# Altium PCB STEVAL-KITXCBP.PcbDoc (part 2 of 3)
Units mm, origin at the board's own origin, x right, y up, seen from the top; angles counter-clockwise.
Board outline 265 x 224 mm, 4 copper layers (Top Layer, GND, PWR, Bottom Layer), stack 1.55 mm thick; 241 components, 114 nets, 595 pads, 236 vias.
Unrouted connection lines stored in the file: 2.
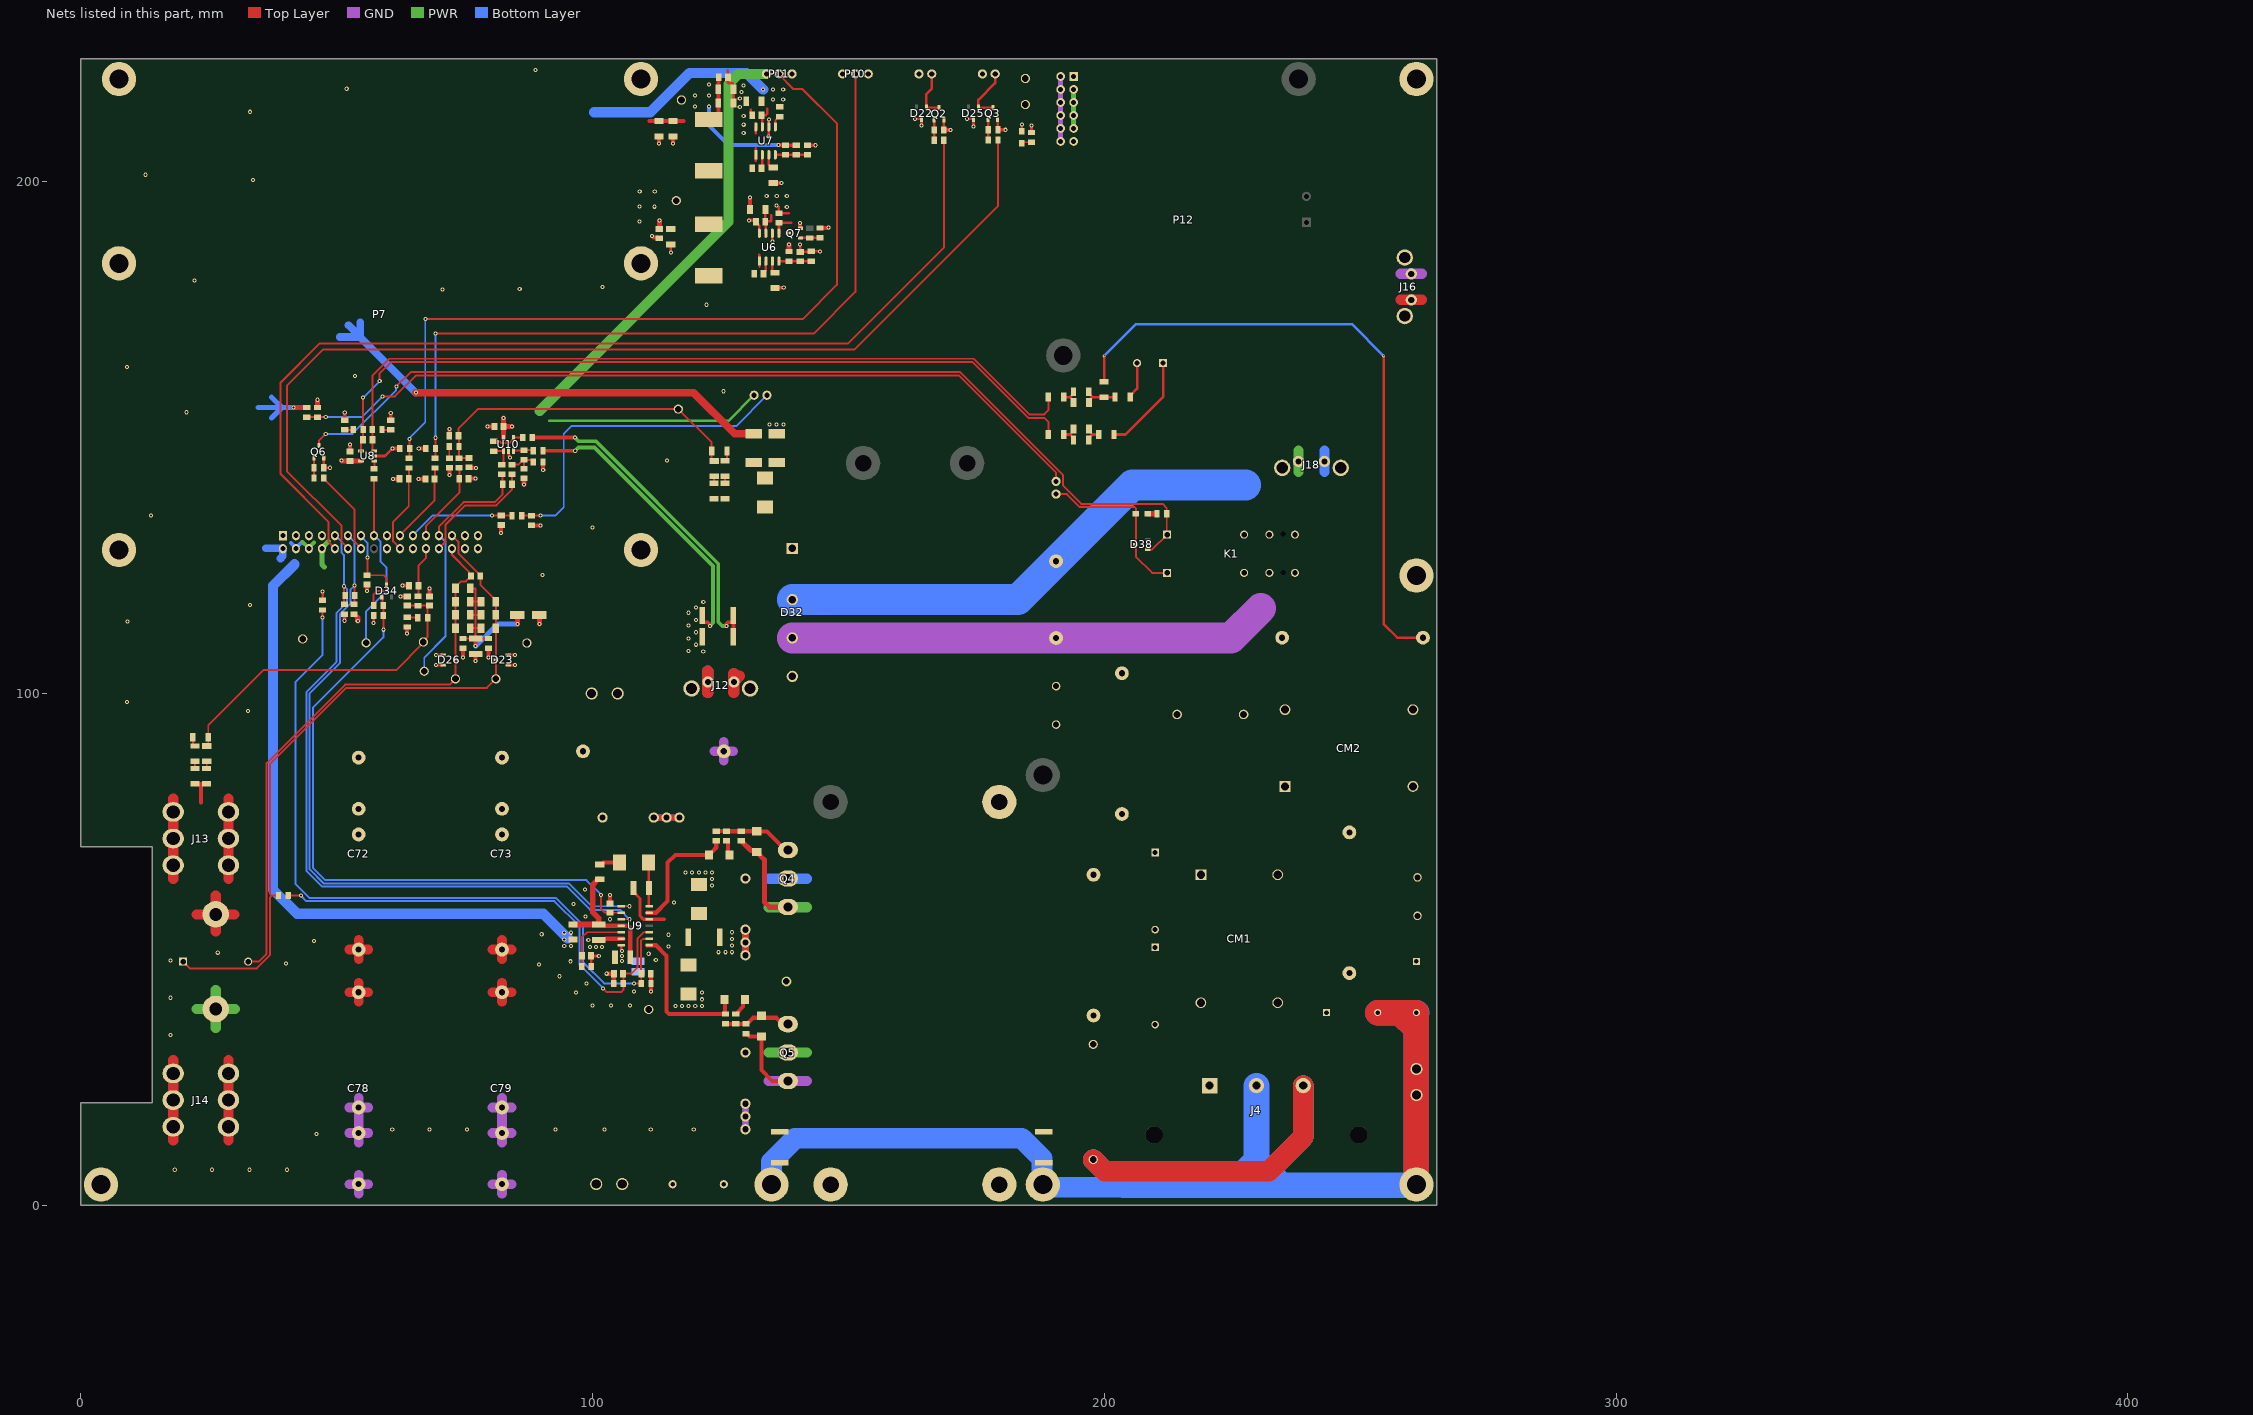
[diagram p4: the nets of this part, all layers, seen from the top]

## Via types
v1: diameter 0.8, hole 0.4, Top Layer to Bottom Layer, tented both sides, 234 vias
v2: diameter 0.6, hole 0.3, Top Layer to Bottom Layer, tented both sides, 2 vias

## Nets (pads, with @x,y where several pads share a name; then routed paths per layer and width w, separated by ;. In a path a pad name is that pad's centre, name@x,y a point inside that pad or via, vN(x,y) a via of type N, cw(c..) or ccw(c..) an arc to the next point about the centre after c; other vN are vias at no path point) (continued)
+3V3: C55.1 C84.2 D23.2 D26.2 P7.8 P9.2 P10.1 P11.1 R70.2 R79.2 R84.2 R93.2 R101.2 U8.5 U10.5 | length 154.8
  Top Layer w0.5: R70.2@47.3,118.15 v1(47.3,119.851) ; v1(57.251,113.749) R93.2@57.251,115.196
  Top Layer w0.6: v1(69.482,105.55) D26.2@70.85,105.55 ; D23.2@83.55,107.45 v1(84.918,107.45)
  Top Layer w0.762: v1(79.7,107.013) R79.2@79.7,108.8
  Top Layer w1: v1(51.018,145.451) 51.064,145.406 C55.1@52.648,145.406 U8.5@54.802,145.406 ; R84.2@53.45,115.45 54.161,114.739 54.161,114.104 v1(54.164,114.101) ; U10.5@82.658,149.92 82.664,149.925 82.664,152.113 C84.2@82.669,152.119 ; v1(82.658,153.744) 82.669,153.734 C84.2@82.669,152.119 ; v1(84.258,152.113) 84.253,152.119 C84.2@82.669,152.119 ; v1(86.656,140.767) R101.2@86.656,141.994
  PWR w0.5: 91.6,153.2 126.575,153.2 P9.2@131.6,158.225
  PWR w1: 47.601,124.683 47.15,125.134 47.15,128.358 48.412,129.62
  PWR w2: 89.7,155.2 126.6,192.1 126.6,219 128.6,221 P11.1@134,221
  other v1: 90.272,123.088
+5V: C40.2 C41.2 C89.2 C91.2 C92.2 C93.2 L4.1 P7.6 R31.2 TP10.1 | length 42
  Top Layer w0.762: 111.173,211.777 C91.2@113.039,211.777 C92.2@115.731,211.777 117.815,211.777 ; L4.1@122.7,212.1 123.519,212.1 124.638,213.219 124.638,220.282 C41.2@124.676,220.32 C41.2@124.498,220.497 ; v1(136.335,207.084) 137.704,207.084 137.727,207.061 139.814,207.061 C93.2@139.837,207.038
  PWR w0.762: 43.398,129.546 44.602,128.342 44.61,128.342 44.61,128.49 45.589,129.469
  Bottom Layer w0.762: v1(122.784,214.651) 122.784,210.928 126.628,207.084 v1(136.335,207.084)
  other v1: 120.04,214.651 120.04,216.782 122.784,216.782 122.784,218.913
+16V: C35.2 C88.2 L3.1 P7.4 R24.2 R81.1 R82.2 R98.2 TP9.1 | length 229
  Top Layer w1: R98.2@46.288,155.832 v1@46.288,157.211 ; C88.2@113.1,190.702 113.1,192.314 v1@113.111,192.325 ; R24.2@138.445,186.306 v1(138.445,187.647)
  Top Layer w1.5: v1(65.506,158.732) 119.759,158.732 127.791,150.7 R81.1@131.5,150.7
  Bottom Layer w0.762: 41.082,129.33 42.07,128.342 43.182,129.454
  Bottom Layer w1.5: 50.62,169.586 54.652,169.586 ; 52.359,171.879 54.652,169.586 ; 54.652,172.46 54.652,169.586 ; v1(65.506,158.732) 54.652,169.586
  Bottom Layer w2: 41.81,125.19 37.6,120.979 37.6,61.6 42.3,56.9 90.419,56.9 95.173,52.146
  other v1: 94.5,50.608 95.8,50.608 94.5,51.908 94.5,53.208 95.8,53.208 46.288,157.338 109.225,192.131 113.111,192.33 112.172,195.056 109.236,195.067 109.247,198.002 112.183,197.991
+24V: C32.2 C33.2 C37.2 C38.2 D1.1 D22.3 D25.3 J8.1 J9.1 P7.2 P12.5 P12.7 P12.9 P12.11 R5.1 R32.1 R99.2 R118.2 TP2.1 U6.7 U7.7 | length 87.4
  Top Layer w0.508: U7.7@133.2,210.652 133.182,210.669 133.182,212.815 C37.2@133.047,212.95 133.872,212.95 134.17,213.248 134.17,214.21 134.173,214.213 ; C32.2@133.786,192.101 133.882,192.004 133.882,189.89 U6.7@133.9,189.872 ; C33.2@133.8,194.513 133.793,194.506 133.793,192.108 133.918,192.234 134.809,192.234 134.981,192.406 134.981,193.41 ; 136.44,194.97 136.449,194.961 R118.2@136.449,193.787 138.361,193.787 ; v1(163.063,212.208) 164.307,212.208 D22.3@164.307,212.108 164.307,210.964 v1@164.296,210.953 ; v1@173.214,212.227 174.458,212.227 D25.3@174.458,212.127 v1(174.458,210.709) ; D1.1@183.9,209.718 v1(183.9,211.136)
  Top Layer w1: v1(41.6,155.8) 41.616,155.816 44.189,155.816 R99.2@44.205,155.832
  PWR w1: P12.11@194.032,210.347 P12.9@194.032,212.887 P12.7@194.032,215.427 P12.5@194.032,217.967
  Bottom Layer w1: 34.7,155.853 34.753,155.8 39.361,155.8 ; 37.33,153.768 39.361,155.8 ; 37.33,157.832 39.361,155.8 ; v1(41.6,155.8) 39.361,155.8
  Bottom Layer w1.5: 36.177,128.342 39.53,128.342 39.53,126.796 39.063,126.33
  Bottom Layer w2: 100.3,213.5 111.324,213.5 119.024,221.2 130.095,221.2 v1(133.361,217.934)
  other v1: 134.594,152.487 136,152.487 137.3,152.487 137.983,194.97 135.941,195.314 134.061,197.155 136.022,197.155 137.983,197.155 164.307,210.943 173.203,212.237 135.322,216.004 137.283,216.004 135.322,217.934 137.283,217.934
CP+: C67.1 R71.1 R73.2 U9.10 | length 92.9
  Top Layer w0.381: R71.1@40.578,60.448 v1(43.067,60.448) ; v1(102.1,42.32) 102.82,41.6 105.631,41.6 106.05,42.019 R73.2@106.05,43.3 106.05,45.15 C67.1@106,45.2 107.591,45.2 108.8,46.409 108.8,52.069 110.034,53.303 U9.10@111.094,53.303
  Bottom Layer w0.381: v1(43.067,60.448) 44.115,59.4 92.594,59.4 97.5,54.494 97.5,46.92 v1(102.1,42.32)
CP-: C66.1 R70.1 R72.2 U9.9 | length 145
  Top Layer w0.381: v1(47.264,114.81) 47.264,116.214 R70.1@47.3,116.25 ; v1(108.115,43.3) R72.2@109.55,43.3 109.55,45.15 C66.1@109.6,45.2 ; C66.1@109.494,45.825 109.494,51.596 109.921,52.023 111.085,52.023 U9.9@111.094,52.033
  Bottom Layer w0.381: v1(47.264,114.81) 47.264,107.464 42.018,102.218 42.018,62.714 44.698,60.035 92.857,60.035 98.2,54.692 98.2,47.387 102.287,43.3 v1(108.115,43.3)
Fan1_PWM: P7.10 R68.1 | length 198.2
  Top Layer w0.381: P7.10@49.69,128.342 48.412,129.62 48.412,133.488 39.065,142.835 39.065,160.68 46.736,168.351 149.951,168.351 168.66,187.06 R68.1@168.66,208.044
Fan2_PWM: P7.12 R75.1 | length 203.1
  Top Layer w0.381: P7.12@52.23,128.342 51,129.573 51,132.693 40.3,143.393 40.3,160.1 47.332,167.132 151.181,167.132 179.26,195.211 R75.1@179.26,208.063
GND: C1.2 C4.2 C32.1 C33.1 C34.1 C35.1 C37.1 C38.1 C39.1 C40.1 C41.1 C48.2 C54.2 C55.2 C56.2 C57.2 C58.2 C59.2 C60.2 C61.2 C66.2 C67.2 C69.2 C70.1 C80.2 C81.2 C84.1 C86.2 C88.1 C89.1 C91.1 C92.1 C94.1 D23.1 D26.1 NT1.2 NT2.2 P7.1 P7.3 P7.5 P7.7 P7.17 P7.18 P7.29 P7.30 P7.31 P7.32 P10.3 P11.3 P12.3 P12.4 P12.6 P12.8 P12.10 P12.12 P12.13 P12.14 Q2.2 Q3.2 Q6.2 Q7.2 R6.1 R27.1 R33.1 R37.1 R52.1 R63.2 R64.2 R66.1 R67.2 R69.1 R72.1 R73.1 R78.1 R80.2 R89.1 R96.2 R102.1 R114.2 R120.1 R122.1 TP3.1 TP20.1 TP25.1 U6.6 U6.8 U7.6 U7.8 U8.2 U9.6 U10.2 | length 136.2
  Top Layer w0.508: Q6.2@47.514,145.985 R122.1@47.514,144.05 v1(48.768,144.05) ; U8.2@57.402,146.356 59.481,146.356 v1(60.966,147.841) ; U10.2@83.608,147.32 83.654,147.274 83.654,146.336 v1@84.018,145.972 ; v1@115.3,186.154 C35.1@115.3,187.7 ; 126.479,221.745 C41.1@126.479,220.32 126.479,219.342 126.619,219.202 127.386,219.202 ; C89.1@127.612,215.138 C40.1@127.612,217.83 ; 130.939,214.021 130.939,213.255 C37.1@131.244,212.95 ; 131.93,209.428 U7.8@131.93,210.652 ; C32.1@132.212,192.407 131.982,191.936 132.287,191.631 132.332,191.631 132.63,191.333 U6.8@132.63,189.872 ; v1(134.417,208.788) 134.47,208.841 U7.6@134.47,210.652 ; v1@135.17,188.281 U6.6@135.17,189.872 ; v1(140.578,187.647) C94.1@140.578,186.222 140.628,186.272 142.713,186.272 R27.1@142.763,186.322 v1(144.464,186.322) ; R69.1@168.66,210.065 168.668,210.072 168.668,212.048 Q2.2@168.676,212.055 ; Q3.2@179.191,212.074 179.225,212.039 179.225,210.118 R78.1@179.26,210.084 ; R6.1@185.8,209.493 v1(185.8,210.911)
  Top Layer w0.538: C80.2@99.752,48.687 C80.2@99.764,48.675 ; R96.2@99.802,46.63 99.777,46.655 99.777,48.662 C80.2@99.764,48.675 ; v1(101.252,48.662) 101.239,48.675 C80.2@99.764,48.675 ; U7.6@134.47,210.652 v1(134.47,212.125)
  Top Layer w0.6: v1(69.482,107.45) D26.1@70.85,107.45 ; D23.1@83.55,105.55 v1(84.918,105.55)
  Top Layer w0.762: v1(51.6,114.161) R89.1@51.6,115.45 ; R67.2@51.613,153.355 v1(51.613,154.885) ; C55.2@52.648,147.206 v1(52.648,148.584) ; v1(55.969,119.958) C4.2@55.969,121.247 ; R66.1@60.604,153.405 v1(60.604,154.784) ; v1(60.966,147.841) R52.1@62.345,147.841 ; v1(61.062,141.872) C54.2@62.32,141.872 ; v1(62.523,118.933) C60.2@63.901,118.933 ; v1(62.922,121.03) C61.2@64.299,121.03 ; v1(63.815,111.655) R64.2@63.815,113.033 ; v1(65.996,141.858) C48.2@67.374,141.858 ; v1(66.071,147.827) R37.1@67.449,147.827 ; C59.2@68.169,118.833 v1(68.169,120.456) ; C56.2@72.044,150.266 v1(72.044,151.645) ; v1(72.065,142.612) R63.2@72.065,143.99 ; v1(74.7,107.013) R80.2@74.7,108.8 ; C58.2@75.795,141.93 v1(77.174,141.93) ; C57.2@75.896,144.04 v1(77.274,144.04) ; v1(77.2,106.3) C69.2@77.2,107.7 ; v1(79.491,152.119) C84.1@80.869,152.119 ; v1(82.166,131.315) C86.2@82.166,132.889 ; R114.2@88.1,132.789 v1(89.887,132.789) ; R102.1@90.361,145.191 90.361,143.614 v1(90.391,143.584) ; C81.2@103.448,58.913 103.46,58.925 103.46,60.589 v1(103.471,60.601) ; v1(111.626,189.347) 111.695,189.347 111.965,189.076 112.922,189.076 C88.1@113.1,188.898 ; v1(113.039,207.366) C91.1@113.039,208.777 ; v1(115.731,207.366) C92.1@115.731,208.777 ; v1@130.621,192.407 C32.1@132.212,192.407 ; C33.1@130.8,194.513 v1(130.8,196.88) ; C39.1@135.316,199.702 v1@136.908,199.702 ; C34.1@135.788,179.222 v1@137.38,179.222 ; Q7.2@140.578,190.924 v1(140.578,191.887) ; R33.1@142.001,207.067 143.555,207.067 v1(143.561,207.061) ; R120.1@144.49,190.894 144.553,190.957 144.585,190.925 146.12,190.925 v1(146.152,190.957) ; R69.1@168.66,210.065 169.978,210.065 v1@169.986,210.072 ; R78.1@179.26,210.084 v1(180.696,210.084)
  Top Layer w0.8: C70.1@101.252,51.803 101.427,51.978 102.616,51.978 102.671,52.033 U9.6@105.652,52.033 U9.6@106.1,52.033 ; v1(102.8,45.2) C67.2@104.2,45.2 104.175,45.175 104.175,43.325 R73.1@104.15,43.3 ; C66.2@111.4,45.2 111.425,45.175 111.425,43.325 R72.1@111.45,43.3 v1(111.45,41.723)
  Top Layer w1: v1(89.632,113.513) C1.2@89.632,115.3
  GND w1: P12.14@191.492,207.807 P12.12@191.492,210.347 P12.10@191.492,212.887 P12.8@191.492,215.427 P12.6@191.492,217.967 P12.4@191.492,220.507
  Bottom Layer w1: P12.14@191.492,207.807 P12.12@191.492,210.347 P12.10@191.492,212.887 P12.8@191.492,215.427 P12.6@191.492,217.967 P12.4@191.492,220.507
  other v1: 108.115,41.723 98.852,43.3 95.692,47.629 99.5,50.4 100.7,50.4 101.9,50.4 99.2,51.8 90.1,52.907 103.471,55.843 98.683,56.338 96.272,58.817 98.589,61.617 32.7,96.5 9.1,98.3 9.2,114 33.1,117.2 100,132.4 13.8,134.7 114.6,145.5 83.883,146.031 20.7,154.9 125.6,159 53.6,162.006 9.1,163.7 122.3,175.9 70.7,178.9 85.8,179 137.391,179.233 102,179.4 22.3,180.6 115.32,186.134 135.181,188.27 130.579,192.355 136.919,199.713 33.7,200.3 12.7,201.3 129.564,209.428 169.982,210.068 129.564,211.077 129.564,212.815 33.1,213.6 128.8,214.5 128.8,216.2 129.1,217.5 52,218.1 129.497,218.73 88.9,221.8
Heatsink_Temp_p: C86.1 P7.21 R113.2 | length 20.9
  Top Layer w0.381: v1(80.38,134.689) C86.1@82.166,134.689 R113.2@84.303,134.689
  Bottom Layer w0.381: P7.21@64.93,130.882 68.737,134.689 v1(80.38,134.689)
HS_1: HS_1.1 R107.2
HS_2: HS_2.1 R108.2
HS_3: HS_3.1
IACn: C68.2 D26.3 P7.28 R2.1 R3.2 R4.1 R8.2 TP1.1 TR1.3 | length 113.5
  Top Layer w0.381: TR1.3@32.754,47.556 34.856,47.556 36.365,49.065 36.365,86.344 51.708,101.686 72.136,101.686 TP1.1@73.25,102.8 D26.3@73.25,106.5 R3.2@73.25,112.7 R2.1@73.25,115.3 R4.1@73.25,117.9 R8.2@73.25,119.765 ; P7.28@72.55,128.342 72.582,128.31 72.582,127.005 75.915,123.672 75.915,123.284 C68.2@76.3,122.9 76.3,122.75 75.915,122.365 75.765,122.365 75.269,121.869 74.349,121.869 73.714,121.234 73.71,121.234 73.25,120.775 R8.2@73.25,120.5
IACp: C68.1 D23.3 P7.27 R71.2 R74.2 R76.1 R77.2 TP15.1 TR1.1 | length 140.2
  Top Layer w0.381: TR1.1@20.054,47.556 21.357,46.253 34.451,46.253 37,48.802 37,60.055 37.393,60.448 ; R71.2@38.678,60.448 37.393,60.448 ; P7.27@72.55,130.882 73.8,129.633 73.8,127.35 78.1,123.05 C68.1@78.1,122.9 78.1,121.225 81.15,118.175 R76.1@81.15,117.9 R74.2@81.15,115.3 R77.2@81.15,112.7 D23.3@81.15,106.5 TP15.1@81.15,102.8 79.38,101.031 51.95,101.031 37,86.081 37,60.842 37.393,60.448
IDCn: C83.1 P7.26 R106.1 | length 23.9
  Top Layer w0.381: P7.26@70.01,128.342 71.3,129.632 71.3,132.886 75.117,136.703 81.224,136.703 84.275,139.753 C83.1@84.275,140.861 ; R106.1@84.275,142.768 C83.1@84.275,140.861 ; C83.1@84.28,140.866 C83.1@84.275,140.861
IDCp: C83.2 P7.25 R110.1 TP22.1 | length 49.8
  Top Layer w0.381: P7.25@70.01,130.882 70.01,132.494 74.854,137.338 80.961,137.338 82.48,138.856 C83.2@82.48,140.866 82.48,142.594 R110.1@82.306,142.768 ; R110.1@82.306,142.92 R110.1@82.48,142.747
  Bottom Layer w0.381: TP22.1@67.148,104.3 67.148,106.976 71.3,111.128 71.3,129.593 P7.25@70.01,130.882
LINEen: P7.14 R111.1 | length 16.7
  Top Layer w0.381: R111.1@47.514,142.069 47.514,141.894 53.543,135.864 53.543,129.569 P7.14@54.77,128.342
NetC1_1: C1.1 C69.1 R2.2 R3.1 R4.2 R8.1 R74.1 R76.2 R77.1 R79.1 R80.1 | length 35.4
  Top Layer w0.381: R80.1@74.7,110.7 C69.1@77.2,110.7 ; R3.1@76.15,112.7 77.2,112.7 ; R2.2@76.15,115.3 77.2,115.3 ; R4.2@76.15,117.9 77.2,117.9 ; R8.1@76.15,120.5 77.2,120.5 77.2,117.9 ; R77.1@78.25,112.7 77.2,112.7 ; R74.1@78.25,115.3 77.2,115.3 ; R76.2@78.25,117.9 77.2,117.9 ; R79.1@79.7,110.7 C69.1@77.2,110.7 ; C69.1@77.2,110.7 77.2,112.7 ; 77.2,112.7 77.2,115.3 ; 77.2,115.3 77.2,117.9
  Top Layer w0.762: v1(77.2,109.2) C69.1@77.2,110.7
  Top Layer w1: v1(85.332,113.513) C1.1@85.332,115.3
  Bottom Layer w1: v1(77.2,109.2) 81.513,113.513 v1(85.332,113.513)
NetC2_2: C2.2 C70.2 R82.1 R83.1 U9.4 | length 27.3
  Top Layer w0.8: C70.2@101.252,54.803 101.427,54.628 102.616,54.628 102.671,54.573 U9.4@105.652,54.573 106.931,54.573 107.4,54.104 C2.2@107.4,48.4
  Top Layer w1.05: C70.2@101.252,54.803 101.252,56.005 100.076,57.181 100.076,62.626 101.1,63.65 R83.1@101.425,63.65
  Top Layer w1.15: R82.1@96.2,54.8 96.525,54.8 96.528,54.803 C70.2@101.252,54.803
NetC29_1: C29.1 U6.2 | length 2.7
  Top Layer w0.508: C29.1@133.415,181.968 133.415,182.133 133.9,182.618 U6.2@133.9,184.422
NetC29_2: C29.2 L3.2 U6.1 | length 2.4
  Top Layer w0.381: 132.63,183.227 U6.1@132.63,184.422
  Top Layer w0.508: U6.1@132.63,184.422 132.63,185.631
NetC34_2: C34.2 U6.3 | length 2.6
  Top Layer w0.508: U6.3@135.17,184.422 135.17,182.48 135.491,182.159 C34.2@135.668,182.159
NetC36_1: C36.1 U7.2 | length 2.7
  Top Layer w0.508: C36.1@133.03,202.542 133.182,202.694 133.182,205.184 U7.2@133.2,205.202
NetC36_2: C36.2 L4.2 U7.1 | length 2.4
  Top Layer w0.508: 131.93,204.01 U7.1@131.93,205.202 131.93,206.431
NetC39_2: C39.2 U7.3 | length 3
  Top Layer w0.508: U7.3@134.47,205.202 134.47,203.223 134.991,202.702 C39.2@135.316,202.702
NetC44_1: C44.1 C46.1 CM1.4 CM2.1 VR1.2
NetC44_2: C44.2 C47.1 CM1.3 CM2.2 VR1.1
NetC49_1: C49.1 R47.1 R53.2 | length 3.9
  Top Layer w0.508: R53.2@192.1,157.85 193.3,157.85 ; R47.1@194,158.9 194,158.55 193.3,157.85 ; C49.1@194.025,156.8 194.025,157.125 193.3,157.85
NetC49_2: C49.2 R7.2 R38.1 R47.2 | length 7.1
  Top Layer w0.508: C49.2@196.975,156.8 196.975,157.125 197.7,157.85 ; R47.2@197,158.9 197,158.55 197.7,157.85 ; R38.1@202.1,157.85 R7.2@200,157.85 197.7,157.85
NetC50_1: C50.1 R48.2 R54.1 | length 3.9
  Top Layer w0.508: R54.1@192.1,150.55 193.3,150.55 ; C50.1@194,151.6 194,151.25 193.3,150.55 ; R48.2@194.025,149.5 194.025,149.825 193.3,150.55
NetC50_2: C50.2 R39.2 R48.1 | length 3.9
  Top Layer w0.508: R48.1@196.975,149.5 196.975,149.825 197.7,150.55 ; C50.2@197,151.6 197,151.25 197.7,150.55 ; R39.2@198.9,150.55 197.7,150.55
NetC51_1: C51.1 R42.1 | length 1.4
  Top Layer w0.381: R42.1@123.8,141 C51.1@123.8,142.4
NetC51_2: C51.2 C56.1 C57.1 R49.1 R55.2 R58.2 TP11.1 | length 65.4
  Top Layer w0.381: C57.1@75.896,145.94 R55.2@73.929,145.94 R58.2@73.929,148.23 73.929,150.182 C56.1@73.844,150.266 73.844,151.757 77.598,155.511 TP11.1@116.789,155.511 123.3,149 123.3,145.785 123.684,145.4 C51.2@123.8,145.4
NetC52_1: C52.1 R46.1 | length 1.4
  Top Layer w0.381: R46.1@24.65,85.3 C52.1@24.65,86.7
NetC52_2: C52.2 C59.1 C60.1 R50.1 R56.2 R59.2 TP12.1 | length 65
  Top Layer w0.381: C52.2@24.65,89.7 24.95,90 R50.1@24.95,91.4 24.95,93.75 35.7,104.5 61.65,104.5 66.98,109.83 TP12.1@66.98,110.022 66.98,110.214 67.799,111.032 R59.2@67.799,114.731 67.799,116.762 C59.1@68.169,117.133 C60.1@63.801,117.133
NetC76_1: C76.1 D32.2 K1.21 | length 97.8
  Bottom Layer w6: D32.2@139.062,118.297 183.137,118.297 205.503,140.663 227.635,140.663
NetC76_2: C76.2 D32.3 K1.11 | length 93.8
  GND w6: D32.3@139.062,110.797 193.622,110.797 ; 193.749,110.797 199.742,110.797 ; 199.742,110.796 224.784,110.796 230.576,116.589
NetC80_1: C80.1 R96.1 U9.5 | length 13.8
  Top Layer w0.381: R96.1@97.902,46.63 C80.1@97.902,48.687 ; C80.1@97.952,48.687 97.952,52.292 98.963,53.303 U9.5@105.652,53.303
NetC81_1: C81.1 D34.1 R92.2 R93.1 U9.2 | length 124.8
  Top Layer w0.381: D34.1@58.85,118.779 58.96,118.67 58.96,117.346 R92.2@59.15,117.155 R93.1@59.15,115.196 v1(59.15,112.408) ; v1(101.7,60.6) 101.7,57.791 102.375,57.116 103.445,57.116 C81.1@103.448,57.113 U9.2@106.188,57.113
  Bottom Layer w0.381: v1(59.15,112.408) 59.15,110.92 45.4,97.17 45.4,65.871 47.801,63.47 98.83,63.47 v1(101.7,60.6)
NetC87_1: C87.1 D28.1 D36.2 R90.2 U9.12 | length 11
  Top Layer w0.6: C87.1@108.052,61.93 108.052,61.155 109.3,59.907 109.3,56.5 109.957,55.843 U9.12@111.094,55.843 114.091,55.843
NetC87_2: C87.2 D29.2 U9.14 | length 8.6
  Top Layer w0.5: D29.2@110.977,66.93 111.052,66.855 C87.2@111.052,61.93 111.052,58.412 111.081,58.383 U9.14@111.094,58.383
NetC93_1: C93.1 R31.1 R33.2 U7.4 | length 6.3
  Top Layer w0.508: U7.4@135.74,205.202 135.748,205.194 141.993,205.194 R33.2@142.001,205.186
NetC94_2: C94.2 R24.1 R27.2 U6.4 | length 6.3
  Top Layer w0.508: U6.4@136.44,184.422 136.448,184.414 138.437,184.414 R24.1@138.445,184.406 138.452,184.414 142.755,184.414 R27.2@142.763,184.422
NetD1_2: D1.2 R6.2 | length 2
  Top Layer w0.381: D1.2@183.9,207.425 184.125,207.65 R6.2@185.8,207.65
NetD22_1: D22.1 J8.2 Q2.3 | length 9.4
  Top Layer w0.508: D22.1@165.257,214.408 167.68,214.408 Q2.3@167.726,214.455 Q2.3@167.726,214.455 ; D22.1@165.257,214.508 165.257,217.05 166.3,218.093 J8.2@166.3,221
NetD25_1: D25.1 J9.2 Q3.3 | length 10.7
  Top Layer w0.508: D25.1@175.408,214.427 178.195,214.427 178.241,214.473 Q3.3@178.241,214.474 ; D25.1@175.408,214.527 175.408,215.908 178.7,219.2 J9.2@178.7,221
NetD27_1: D27.1 R5.2 R81.2
NetD29_1: D29.1 R83.2 | length 4.1
  Top Layer w0.8: R83.2@101.425,66.55 101.75,66.55 102.13,66.93 D29.1@105.327,66.93
NetD30_1: D30.1 R88.2 | length 3.1
  Top Layer w0.8: R88.2@126.2,71.15 126.375,71.15 126.5,71.025 126.5,68.715 D30.1@126.815,68.4
NetD31_2: D31.2 Q4.1 R85.2 R87.1 R88.1 | length 14.7
  Top Layer w0.8: R85.2@124.2,73.05 R88.1@126.2,73.05 ; 127,73.033 129.1,73.033 132.082,73.033 D31.2@132.1,73.015 134.143,73.015 137.847,69.311 Q4.1@138.184,69.311
NetD32_4: D32.4 J12.2 R97.2 R100.2 R112.1 | length 71.2
  Top Layer w0.762: R112.1@88.288,149.934 v1(96.614,149.934) ; v1(126.177,113.119) 126.226,113.167 126.226,113.562 126.525,113.862 127.376,113.862 R97.2@127.545,114.031 ; R100.2@127.545,111.015 127.545,112.967 ; R97.2@127.545,115.181 R97.2@127.545,114.031 ; 127.547,112.966 127.545,112.967 ; 127.545,112.967 R97.2@127.545,114.031
  Top Layer w2.2: 127.64,100.119 J12.2@127.64,102.2 J12.2@127.64,102.285 ; 127.64,103.841 J12.2@127.64,102.285 ; 128.74,103.385 J12.2@127.64,102.285
  PWR w0.762: v1(96.614,149.934) 97.32,149.228 100.672,149.228 124.6,125.3 124.6,113.9 125.374,113.126 126.17,113.126 v1(126.177,113.119)
NetD33_1: D33.1 R94.2 | length 3.7
  Top Layer w0.8: R94.2@128.016,37.319 128.191,37.319 128.316,37.444 128.316,37.619 129.457,38.76 129.457,39.81 D33.1@129.831,40.184
NetD35_2: D35.2 Q5.1 R91.2 R94.1 R95.1 | length 13.5
  Top Layer w0.8: R91.2@126.016,35.419 126.045,35.389 R95.1@130.016,35.389 130.191,35.389 131.388,36.587 132.616,36.587 D35.2@133.016,36.987 133.416,36.587 135.958,36.587 137.185,35.36 Q5.1@138.184,35.36
NetD37_1: D37.1 D38.3 J20.2 K1.A1 | length 33.6
  Top Layer w0.381: J20.2@190.6,138.9 192.7,138.9 195.235,136.365 205.958,136.365 206.181,136.142 206.181,129.068 206.181,126.696 209.371,123.506 K1.A1@212.275,123.506
NetD37_2: D37.2 R104.2 | length 1.7
  Top Layer w1: D37.2@208.531,135.074 R104.2@210.189,135.074
NetD38_1: D38.1 K1.A2 Q6.3 R104.1 | length 194.9
  Top Layer w0.381: Q6.3@46.564,148.385 46.564,149.329 v1(47.904,150.669) ; v1(61.709,159.931) 64.513,162.735 171.845,162.735 191.955,142.625 191.955,140.543 195.498,137 211.397,137 212.218,136.179 212.218,131.063 K1.A2@212.275,131.006 209.387,128.118 D38.1@208.5,128.118
  Bottom Layer w0.381: v1(47.904,150.669) 53.103,150.669 61.655,159.221 61.655,159.877 v1(61.709,159.931)
NetF1_1: F1.1 J4.3 | length 164.4
  Top Layer w4: F1.1@197.851,8.892 200.137,6.606 232.192,6.606 238.879,13.294 J4.3@238.879,23.343
  GND w4: F1.1@197.851,8.892 200.137,6.606 232.192,6.606 238.879,13.294 J4.3@238.879,23.343
  PWR w4: F1.1@197.851,8.892 200.137,6.606 232.192,6.606 238.879,13.294 J4.3@238.879,23.343
NetJ20_1: J20.1 R98.1 R99.1 | length 159.5
  Top Layer w0.381: R99.1@44.364,153.773 R99.1@44.205,153.932 R98.1@46.288,153.932 v1(47.904,153.932) ; v1(59.005,157.988) 61.429,157.988 65.541,162.1 171.582,162.1 190.6,143.082 J20.1@190.6,141.4
  Bottom Layer w0.381: v1@47.918,153.932 54.949,153.932 v1(59.005,157.988)
NetP9_1: P9.1 R113.1 R114.1 | length 66.1
  Top Layer w0.381: R113.1@86.203,134.689 R114.1@88.1,134.689 v1(89.887,134.689)
  Bottom Layer w0.381: v1(89.887,134.689) 92.789,134.689 94.4,136.3 94.4,150.7 95.9,152.2 128.075,152.2 P9.1@134.1,158.225
NetP10_2: P10.2 R36.2 R37.2 | length 152.4
  Top Layer w0.381: R36.2@69.249,145.895 69.349,145.995 R37.2@69.349,147.827 v1(69.349,149.911) ; v1(69.349,170.26) 143.26,170.26 151.4,178.4 P10.2@151.4,221
  Bottom Layer w0.381: v1(69.349,149.911) v1(69.349,170.26)
NetP11_2: P11.2 R43.2 R52.2 | length 158.6
  Top Layer w0.381: R43.2@64.195,145.909 64.295,146.009 R52.2@64.295,147.841 v1(64.295,149.708) ; v1(67.4,173.1) 141.108,173.1 147.777,179.769 147.777,211.322 141.044,218.055 139.286,218.055 136.5,220.841 P11.2@136.5,221
  Bottom Layer w0.381: v1(64.295,149.708) 64.295,149.879 67.342,152.927 67.342,173.042 v1(67.4,173.1)
NetQ2_1: Q2.1 R68.2 R69.2 | length 4
  Top Layer w0.508: R68.2@166.76,208.044 R69.2@166.76,210.065 166.768,210.072 166.768,212.048 Q2.1@166.776,212.055
NetQ3_1: Q3.1 R75.2 R78.2 | length 4
  Top Layer w0.508: Q3.1@177.291,212.074 177.325,212.039 177.325,208.097 R75.2@177.36,208.063
NetQ6_1: Q6.1 R111.2 R122.2 | length 3.9
  Top Layer w0.381: R111.2@45.614,142.069 Q6.1@45.614,145.985
NetQ7_1: Q7.1 R119.1 R120.2 | length 3.9
  Top Layer w0.508: Q7.1@140.661,188.943 140.686,188.968 144.464,188.968 R120.2@144.49,188.994
NetQ7_3: Q7.3 R118.1 U6.5 | length 4.5
  Top Layer w0.508: U6.5@136.458,189.764 R118.1@136.458,191.878 ; R118.1@136.458,191.896 138.821,191.894
NetR1_1: R1.1 U8.1 | length 1.6
  Top Layer w0.381: R1.1@57.353,143.835 57.402,143.884 U8.1@57.402,145.406
NetR32_2: R32.2 U7.5 | length 2.5
  Top Layer w0.381: U7.5@135.74,210.652 135.74,211.965 136.425,212.65 R32.2@136.6,212.65
NetR34_1: R34.1 R35.2
NetR40_1: R40.1 R44.2 | length 1.4
  Top Layer w0.381: R40.1@125.9,141 R44.2@125.9,142.4
NetR41_1: R41.1 R45.2 | length 1.4
  Top Layer w0.381: R41.1@22.35,85.3 R45.2@22.35,86.7
NetR44_1: R44.1 R49.2 | length 2.1
  Top Layer w0.381: R44.1@125.9,145.4 125.966,145.4 126.3,145.735 R49.2@126.3,147.3
NetR45_1: R45.1 R50.2 | length 1.9
  Top Layer w0.381: R50.2@21.95,91.4 21.95,90.035 22.284,89.7 R45.1@22.35,89.7
NetR58_1: R58.1 R63.1 | length 2.3
  Top Layer w0.381: R58.1@72.029,148.23 72.029,145.976 R63.1@72.065,145.94
NetR59_1: R59.1 R64.1 | length 2.1
  Top Layer w0.381: R64.1@63.815,114.833 65.797,114.833 R59.1@65.899,114.731
NetR61_1: R61.1 R66.2 | length 1.7
  Top Layer w0.381: R61.1@58.902,151.503 58.949,151.455 R66.2@60.604,151.455
NetR62_1: R62.1 R67.1 | length 1.7
  Top Layer w0.381: R67.1@51.613,151.455 53.255,151.455 R62.1@53.302,151.503
NetR101_1: R101.1 R102.2 R103.2 R106.2 | length 6.5
  Top Layer w0.381: R106.2@84.275,144.668 85.56,144.668 86.481,145.589 R103.2@86.656,145.589 ; R101.1@86.656,143.894 R103.2@86.656,145.589 ; R102.2@88.461,145.191 88.461,145.255 88.127,145.589 R103.2@86.656,145.589
NetR103_1: R103.1 R105.2 U10.3 | length 4
  Top Layer w0.381: U10.3@84.558,147.32 84.643,147.405 86.572,147.405 R103.1@86.656,147.489 88.361,147.489 R105.2@88.461,147.389
NetR110_2: R110.2 R115.2 U10.1 | length 5
  Top Layer w0.381: R115.2@80.532,147.475 R115.2@80.713,147.295 80.725,147.307 82.646,147.307 U10.1@82.658,147.32 82.658,145.002 82.324,144.668 R110.2@82.306,144.668 ; R110.2@82.306,144.82 R110.2@82.324,144.82
NetR112_2: R112.2 R115.1 U10.4 | length 6.3
  Top Layer w0.381: R115.1@80.713,149.195 81.905,149.195 82.174,148.926 83.814,148.926 84.558,149.67 U10.4@84.558,149.92 86.323,149.92 R112.2@86.362,149.959
PE01: H1.1
PE03: C46.2 C47.2 C82.1 H2.1 H3.1 H11.1 J1.1 J4.2 R107.1 R108.1 | length 263.7
  Top Layer w5: C47.2@253.43,37.6 C46.2@261,37.6 J1.1@261,26.571 J1.1@261,21.491 H3.1@261,4 ; 257.818,37.594 260.995,34.417
  Bottom Layer w4.064: H2.1@135,4 135,8.442 139.59,13.032 183.907,13.032 187.854,9.085 187.854,4.146 H11.1@188,4 ; H11.1@188.168,3.832 188.504,3.496 195.566,3.496 195.601,3.46 203.342,3.46 203.745,3.863
  Bottom Layer w5: 203.745,3.863 224.82,3.863 ; J4.2@229.753,23.329 229.753,8.796 ; C47.2@253.43,37.594 257.818,37.594 ; H3.1@260.226,4.212 H3.1@260.644,4.63 ; 260.995,36.77 260.995,34.417 ; C46.2@261.006,37.594 257.818,37.594 ; 224.82,3.863 229.753,3.863 ; 224.82,3.863 229.753,8.796 ; 229.753,3.863 229.753,8.758 ; 229.753,3.863 234.648,3.863 ; 229.753,8.758 229.753,8.796 ; 229.753,8.758 234.648,3.863 ; 234.648,3.863 260.944,3.863 260.995,3.914 260.995,34.417 ; 257.818,37.594 260.995,34.417
PE04: 
PE05: H5.1
PE11: H7.1
PE12: P7.MH
PWM_1H: P7.9 R86.1 R89.2 U9.3 | length 142.2
  Top Layer w0.381: v1(51.463,120.901) 51.463,117.491 R89.2@51.633,117.321 ; U9.3@105.652,55.843 v1(107.242,55.844)
  Bottom Layer w0.381: P7.9@49.69,130.882 51,129.573 51,127.461 51.463,126.998 v1(51.463,120.901) 52.065,120.298 52.065,117.765 50.01,115.71 50.01,106.128 44.1,100.218 44.1,65.3 47.2,62.2 95.042,62.2 99.554,57.688 105.398,57.688 v1(107.242,55.844)
PWM_1L*: P7.11 R84.1 R86.2 U9.1 | length 140.2
  Top Layer w0.381: R86.2@53.483,119.146 53.483,117.35 R84.1@53.493,117.34 ; R86.2@53.533,119.125 v1(53.533,121.012) ; U9.1@105.652,58.383 v1@107.21,58.383
  Bottom Layer w0.381: P7.11@52.23,130.882 53.481,129.632 53.481,121.065 v1(53.533,121.012) 52.7,120.179 52.7,117.5 50.645,115.445 50.645,105.865 44.735,99.955 44.735,65.563 47.463,62.835 95.383,62.835 99.835,58.383 v1(107.242,58.383)
PWM_en/SD*: C4.1 D34.3 P7.13 R92.1 | length 19.8
  Top Layer w0.381: v1(56.052,126.5) 56.052,123.13 C4.1@55.969,123.047 59.232,123.047 59.8,122.479 D34.3@59.8,121.179 59.8,120.199 59.577,119.975 57.896,119.975 57.25,119.329 R92.1@57.25,117.155
  Bottom Layer w0.381: P7.13@54.77,130.882 54.77,130.64 56.052,129.358 v1(56.052,126.5)
TempSens2: C48.1 P7.19 R36.1 | length 16
  Top Layer w0.381: P7.19@62.39,130.882 69.174,137.666 C48.1@69.174,141.858 69.249,141.933 R36.1@69.249,143.995
TempSens3: C54.1 P7.20 R43.1 | length 17.5
  Top Layer w0.381: P7.20@62.39,128.342 61.062,129.671 61.062,133.466 64.12,136.524 C54.1@64.12,141.872 64.195,141.947 R43.1@64.195,144.009
Ubridge: C61.1 P7.24 R56.1 | length 11.5
  Top Layer w0.381: R56.1@65.934,118.983 65.999,119.048 C61.1@65.999,121.03 65.999,124.908 ; 67.035,125.943 65.999,124.908 ; P7.24@67.47,128.342 67.47,126.378 65.999,124.908
Ucap: P7.22
UDC: C58.1 P7.23 R55.1 | length 15.9
  Top Layer w0.381: P7.23@67.47,130.882 67.47,132.647 73.995,139.172 C58.1@73.995,141.93 73.995,143.974 R55.1@73.929,144.04
~AC_L: C43.2 CM1.2 F1.2 R34.2
~AC_N: C43.1 CM1.1 J4.1 R35.1
~Cap: C72.1 C73.1 C78.1 C79.1 J14.1 | length 61.1
  Top Layer w1.9: 52.478,41.579 C78.1@54.334,41.579 ; 52.478,49.913 C72.1@54.334,49.913 ; 54.334,39.722 C78.1@54.334,41.579 ; 54.334,43.436 C78.1@54.334,41.579 ; 54.334,48.057 C72.1@54.334,49.913 ; 54.334,51.77 C72.1@54.334,49.913 ; 56.191,41.579 C78.1@54.334,41.579 ; 56.191,49.913 C72.1@54.334,49.913 ; 80.481,41.579 C79.1@82.338,41.579 ; 80.481,49.913 C73.1@82.338,49.913 ; 82.338,39.722 C79.1@82.338,41.579 ; 82.338,43.436 C79.1@82.338,41.579 ; 82.338,48.057 C73.1@82.338,49.913 ; 82.338,51.77 C73.1@82.338,49.913 ; 84.194,41.579 C79.1@82.338,41.579 ; 84.194,49.913 C73.1@82.338,49.913
  Top Layer w2: 18.1,12.6 J14.1@18.1,15.29 J14.1@18.1,20.5 J14.1@18.1,25.71 18.1,28.3 ; 28.9,12.6 J14.1@28.9,15.29 J14.1@28.9,20.5 J14.1@28.9,25.71 28.9,28.3
~DCbus: C3.1 C72.2 C73.2 C74.1 C75.1 D27.2 D28.2 D32.1 J10.1 J12.1 pad.@112,75.7 pad.@114.5,75.7 Q4.2 R40.2 R42.2 | length 25.7
  Top Layer w1.2: pad.@112,75.7 pad.@114.5,75.7 C3.1@117,75.7
  Top Layer w2.2: 122.56,100.119 J12.1@122.56,102.2 122.56,104.281
  Bottom Layer w1.2: pad.@112,75.7 pad.@114.5,75.7 C3.1@117,75.7
  Bottom Layer w2: 134.507,63.751 138.184,63.751 141.861,63.751
  Bottom Layer w2.2: 122.56,100.119 J12.1@122.56,102.2 122.56,104.281
  other v1: 123.4,62.4 123.4,63.7 118.2,65 119.5,65 120.8,65 122.1,65 123.4,65
~Hbridge: J13.1 R41.2 R46.2 TP18.1 | length 51.8
  Top Layer w0.762: R41.2@22.35,82.3 23.5,82.3 ; 23.5,78.6 23.5,82.3 ; R46.2@24.65,82.3 23.5,82.3
  Top Layer w2: 18.1,63.7 J13.1@18.1,66.39 J13.1@18.1,71.6 J13.1@18.1,76.81 18.1,79.4 ; 22.691,56.791 TP18.1@26.4,56.791 TP18.1@26.424,56.791 ; 26.424,53.5 TP18.1@26.424,56.791 ; 26.424,60.468 TP18.1@26.424,56.791 ; 28.9,63.7 J13.1@28.9,66.39 J13.1@28.9,71.6 J13.1@28.9,76.81 28.9,79.4 ; 30.077,56.791 TP18.1@26.424,56.791
~Hbridge_: C74.2 C77.1 D31.1 pad.@129.9,51.3 pad.@129.9,53.8 Q4.3 Q5.2 R87.2 R90.1 TP17.1 TP19.1 | length 59
  Top Layer w1: R87.2@129.125,71.125 129.3,71.125 129.3,70.95 130.965,69.285 131.8,69.285 133.6,67.485 133.6,59.233 134.642,58.191 Q4.3@138.184,58.191
  Top Layer w1.2: C74.2@129.9,48.8 pad.@129.9,51.3 pad.@129.9,53.8
  PWR w1.2: C74.2@129.9,48.8 pad.@129.9,51.3 pad.@129.9,53.8
  PWR w2: 22.723,38.3 TP17.1@26.4,38.3 ; 26.4,34.591 TP17.1@26.4,38.3 ; 26.4,41.977 TP17.1@26.4,38.3 ; 30.109,38.3 TP17.1@26.4,38.3 ; 134.475,29.8 141.861,29.8 ; 134.476,58.191 Q4.3@138.184,58.191 ; Q4.3@138.105,58.112 Q4.3@138.184,58.191 ; 141.861,58.191 Q4.3@138.184,58.191
  other v1: 124.675,49.4 125.975,49.4 127.275,49.4 127.275,50.7 127.275,52 127.275,53.3
~HighDrive: D30.2 R85.1 U9.13 | length 24.6
  Top Layer w0.8: U9.13@110.646,57.113 U9.13@111.094,57.113 112.43,57.113 114.7,59.383 114.7,66.9 116.2,68.4 D30.2@122.785,68.4 122.785,68.5 123.185,68.9 123.285,68.9 124.2,69.815 R85.1@124.2,71.15
~L_open: J16.1 K1.22 | length 4.2
  GND w2: 257.919,181.94 J16.1@260,181.94 262.081,181.94
~Line: C45.2 J18.1 K1.24 L5.2 P12.2 pad.@234.976,131.075 R38.2 VR2.1 | length 11.4
  Top Layer w0.508: R38.2@205.1,157.85 205.1,158.2 206.42,159.52 P12.2@206.42,164.5
  PWR w2: 237.946,143.219 J18.1@237.946,145.3 237.946,147.381
~Line_pf: C42.1 CM2.3 L5.1 R7.1 | length 126
  Top Layer w0.508: R7.1@200,160.85 v2(200,165.9) ; v2(254.6,165.9) 254.6,113.5 257.252,110.848 C42.1@262.268,110.848
  Bottom Layer w0.508: v2(200,165.9) 206.2,172.1 248.4,172.1 v2(254.6,165.9)
~Line_sens: C65.1 R53.1 R61.2 U8.3 | length 155.9
  Top Layer w0.381: U8.3@57.402,147.306 57.152,147.306 57.042,147.415 57.042,147.665 57.002,147.706 C65.1@57.002,149.531 R61.2@57.002,151.503 57.002,162.006 60.345,165.349 174.551,165.349 185.4,154.5 188.3,154.5 189.1,155.3 R53.1@189.1,157.85
~LowDrive: D33.2 R91.1 U9.8 | length 30.3
  Top Layer w0.8: U9.8@110.646,50.763 U9.8@111.094,50.763 112.437,50.763 114.5,48.7 114.5,37.787 114.969,37.319 R91.1@126.016,37.319 125.908,37.426 125.908,40.076 D33.2@125.801,40.184
~N_open: J16.2 K1.12 | length 4.2
  Top Layer w2: 257.919,176.86 J16.2@260,176.86 262.081,176.86
~Neutral: C42.2 C45.1 CM2.4 J18.2 K1.14 P12.1 pad.@234.976,123.575 R39.1 VR2.2 | length 23.4
  Top Layer w0.508: R39.1@201.9,150.55 204.15,150.55 211.5,157.9 P12.1@211.5,164.5
  Bottom Layer w2: 243.026,143.219 J18.2@243.026,145.3 243.026,147.381
~Neutral_sens: C65.2 R54.2 R62.2 U8.4 | length 155.6
  Top Layer w0.381: U8.4@54.802,147.306 54.802,148.981 55.202,149.381 C65.2@55.202,149.531 R62.2@55.202,151.503 55.221,151.522 v1(55.221,157.741) ; v1(58.446,161) 58.446,162.489 60.657,164.7 174.302,164.7 185.202,153.8 188.3,153.8 189.1,153 R54.2@189.1,150.55
  Bottom Layer w0.381: v1(55.221,157.741) 55.221,157.758 58.446,160.983 v1(58.446,161)
~PGND: C2.1 C3.2 C75.2 C77.2 C78.2 C79.2 C82.2 D35.1 D36.1 J19.1 NT1.1 NT2.1 pad.@129.9,17.3 pad.@129.9,19.8 Q5.3 R95.2 R97.1 R100.1 R105.1 TP21.1 U9.7 | length 147.2
  Top Layer w0.508: U9.7@105.652,50.763 105.652,49.897 105.82,49.729 v1(105.82,49.65)
  Top Layer w0.762: R105.1@90.377,147.374 v1(96.652,147.374) ; R97.1@121.445,115.181 121.445,114.031 121.614,113.862 122.465,113.862 122.923,113.403 122.923,113.216 v1(122.972,113.167)
  Top Layer w0.8: R95.2@130.016,33.489 130.191,33.489 130.723,32.957 D35.1@133.016,32.957 133.016,26.356 135.131,24.24 Q5.3@138.184,24.24
  GND w1.2: C77.2@129.9,14.8 pad.@129.9,17.3 pad.@129.9,19.8
  GND w1.9: 52.478,4.079 C78.2@54.334,4.079 ; 52.478,14.079 C78.2@54.334,14.079 ; 52.478,19.079 C78.2@54.334,19.079 ; 54.334,2.222 C78.2@54.334,4.079 ; 54.334,5.936 C78.2@54.334,4.079 ; 54.334,12.222 C78.2@54.334,14.079 ; 54.334,20.936 C78.2@54.334,19.079 ; 56.191,4.079 C78.2@54.334,4.079 ; 56.191,14.079 C78.2@54.334,14.079 ; 56.191,19.079 C78.2@54.334,19.079 ; 80.481,4.079 C79.2@82.338,4.079 ; 80.481,14.079 C79.2@82.338,14.079 ; 80.481,19.079 C79.2@82.338,19.079 ; 82.338,2.222 C79.2@82.338,4.079 ; 82.338,5.936 C79.2@82.338,4.079 ; 82.338,12.222 C79.2@82.338,14.079 ; 82.338,20.936 C79.2@82.338,19.079 ; 84.194,4.079 C79.2@82.338,4.079 ; 84.194,14.079 C79.2@82.338,14.079 ; 84.194,19.079 C79.2@82.338,19.079 ; 123.818,88.65 C75.2@125.675,88.65 ; 125.675,86.793 C75.2@125.675,88.65 ; 125.675,90.507 C75.2@125.675,88.65 ; 127.532,88.65 C75.2@125.675,88.65 ; C78.2@54.334,14.079 C78.2@54.334,19.079 ; C79.2@82.338,14.079 C79.2@82.338,19.079
  GND w2: 134.475,24.24 141.861,24.24
  PWR w0.762: v1(96.652,147.374) 97.325,148.046 100.417,148.046 123.584,124.879 123.584,113.78 v1(122.972,113.167)
  Bottom Layer w1.2: C77.2@129.9,14.8 pad.@129.9,17.3 pad.@129.9,19.8
  other v1: 18.4,6.9 25.7,6.9 33,6.9 40.3,6.9 46.1,13.859 60.9,14.8 68.2,14.8 75.5,14.8 92.8,14.8 102.4,14.8 111.4,14.8 119.8,14.8 17.592,33.2 116.2,38.9 117.5,38.9 118.8,38.9 120.1,38.9 121.4,38.9 100.049,39 103.625,39 107.349,39 121.4,40.2 17.592,40.5 96.817,41.517 121.4,41.5 93.575,44.7 89.6,47 40.1,47.2 105.82,47.65 17.592,47.8 112.384,47.895 105.82,48.65 111.006,49.1 26.8,49.3 114.9,50.484 45.6,51.6 114.9,52.808 115.968,59.112 121.661,108.176 118.788,108.226 120.228,109.476 118.788,110.726 120.228,111.917 118.788,113.227 120.228,114.272 118.788,115.727 120.228,116.768 121.669,117.809
~Zero_X: P7.15 R1.2 TP14.1 | length 34.8
  Top Layer w0.381: P7.15@57.31,130.882 57.31,141.892 R1.2@57.353,141.935
  Bottom Layer w0.381: TP14.1@55.8,109.831 55.8,115.975 59.8,119.975 59.8,124.517 58.633,125.684 58.633,129.559 P7.15@57.31,130.882
pads on no net: D22.2 D25.2 D34.2 D38.2 H9.1 HS_4.1 HS_5.1 HS_6.1 J4.MH1 J4.MH2 P12. P12.MH U9.11

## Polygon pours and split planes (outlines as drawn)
GND on GND "TOP_LAYER_NONET_P-001" (solid, remove dead copper, pour order 187): 199.6,222 198.145,223.455 4.355,223.455 1.5,220.6 1.5,95.1 3.8,92.8 28.2,92.8 35.1,85.9 35.1,61.178 41.278,55 85.93,55 100.13,40.8 112.638,40.8 113.005,41.167 113.005,45.716 112.621,46.1 104.476,46.1 103.657,46.919 103.657,50.976 104.435,51.754 106.684,51.754 107.954,53.024 107.954,58.843 102.197,64.6 50.85,64.6 48.7,66.75 48.7,95.9 50.4,97.6 79.4,97.6 121.984,140.184 153.395,140.184 199.6,186.389
~PGND on GND "TOP_LAYER_NONET_P-001" (solid, remove dead copper, pour order 198): 142.112,138.229 142.112,126.879 135.733,120.5 127.3,120.5 125.1,118.3 125.1,95.436 128.336,92.2 157.8,92.2 161.296,88.704 161.296,5.096 156.847,0.647 14.102,0.647 14,0.75 14,79.55 15.15,80.7 33.3,80.7 34.091,79.909 34.091,62.187 41.278,55 85.97,55 100.17,40.8 112.638,40.8 113.005,41.167 113.005,46.195 112.1,47.1 104.47,47.1 103.657,47.913 103.657,50.976 104.435,51.754 106.684,51.754 108.9,53.97 108.9,59.345 103.645,64.6 50.85,64.6 48.7,66.75 48.7,95.9 50.407,97.607 79.407,97.607 120.975,139.175 141.166,139.175
~L_open on GND "~L_OPEN_L02_P173" (solid, remove dead copper, pour order 173): 228.978,129.51 228.557,129.088 223.614,129.088 222.875,129.827 222.875,173.723 237.025,187.874 262.827,187.874 263.233,187.467 263.233,181.292 262.832,180.891 241.638,180.891 230.688,169.941 230.688,134.529 228.978,132.819
~AC_L on GND "~AC_L_L02_P160" (solid, remove dead copper, pour order 160): 205.037,39.779 196.886,39.779 195.73,38.623 195.73,30.17 196.891,29.009 203.845,29.009 220.446,29.009 221.778,30.34 221.778,41.404 221.016,42.166 216.444,42.166 214.056,39.779
NetC44_2 on GND "NETC44_2_L02_P153" (solid, remove dead copper, pour order 153): 248.365,32.667 249.97,34.272 249.97,39.904 251.103,41.037 256.008,41.037 256.652,41.658 256.652,59.946 258.532,61.826 263.307,61.826 263.942,62.461 263.942,85.245 263.332,85.854 253.88,85.854 251.877,83.851 251.877,69.598 246.086,63.807 231.049,48.77 231.049,33.947 232.329,32.667
NetC36_2 on Top Layer "TOP_LAYER_NONET_P-001" (solid, pour order 203): 132.23,201.303 131.527,200.6 119.809,200.6 119.313,201.096 119.313,204.387 119.825,204.9 130.012,204.9 130.414,205.302 130.414,206.54 130.651,206.777 132.011,206.777 132.23,206.559
NetC29_2 on Top Layer "NETC29_2_L01_P181" (solid, remove dead copper, pour order 181): 133.242,185.642 133.242,183.258 132.171,182.187 132.171,179.781 130.682,178.293 118.875,178.293 118.128,179.04 118.128,185.019 119.154,186.045 132.839,186.045
+5V on Top Layer "+5V_L01_P176" (solid, remove dead copper, pour order 176): 117.765,211.202 119.171,209.796 126.345,209.796 126.6,210.052 126.6,212.75 125.187,214.163 125.187,222.603 124.37,223.421 116.571,223.421 114.923,221.773 114.923,217.688 110.548,213.314 110.548,211.328 110.674,211.202
+16V on Top Layer "+16V_L01_P169" (solid, remove dead copper, pour order 169): 117.5,189.944 118.506,188.938 125.979,188.938 126.522,189.481 126.522,198.09 125.273,199.339 109.525,199.339 108.306,198.12 108.306,191.211 109.573,189.944
GND on Top Layer "TOP_LAYER_NONET_P-001" (solid, remove dead copper, pour order 195): 131.651,208.524 132.23,209.103 132.23,220.507 130.456,222.281 126.781,222.281 126.5,222 126.5,211 128.976,208.524
+24V on Top Layer "+24V_L01_P182" (solid, remove dead copper, pour order 182): 132.488,218.116 132.834,218.461 137.697,218.461 138.082,218.077 138.082,214.687 137.445,214.05 134.846,214.05 133.5,212.704 133.5,210.227 133.2,209.927 132.488,210.638
NetQ7_3 on Top Layer "NETQ7_3_L01_P180" (solid, remove dead copper, pour order 180): 135.749,188.643 135.749,191.362 135.749,192.412 138.667,192.412 139.461,191.618 139.461,188.838 139.265,188.643
+24V on Top Layer "+24V_L01_P179" (solid, remove dead copper, pour order 179): 133.6,189.447 133.6,191.004 133.227,191.377 133.227,197.232 133.805,197.81 138.476,197.81 138.669,197.617 138.669,193.57 138.361,193.262 135.092,193.262 134.87,193.04 134.87,191.428 134.2,190.758 134.2,189.447 133.9,189.147
~DCbus on Top Layer "TOP_LAYER_NONET_P-001" (solid, remove dead copper, pour order 202): 140.9,138.7 141.6,138 141.6,127.135 135.465,121 120,121 116.4,117.4 116.4,107.702 118.002,106.1 123.4,106.1 123.9,105.6 123.9,79.064 118.036,73.2 101.585,73.2 94.485,66.1 51.573,66.1 50.2,67.473 50.2,95.2 51.1,96.1 80.248,96.1 122.848,138.7
+16V on Top Layer "TOP_LAYER_NONET_P-001" (solid, remove dead copper, pour order 201): 96.71,53.59 96.71,50.226 96.467,49.984 94.324,49.984 93.947,50.362 93.947,53.455 94.3,53.808 96.492,53.808
~PGND on Top Layer "TOP_LAYER_NONET_P-001" (solid, remove dead copper, pour order 200): 103.825,47.05 106.316,47.05 106.379,47.113 106.379,51.042 105.019,51.042 103.825,49.848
